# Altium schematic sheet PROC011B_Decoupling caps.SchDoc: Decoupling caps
size 431 x 279 mm; Date: Not shown in title block; ApprovedBy: Not shown in title block; CheckedBy: Not shown in title block; Author: Not shown in title block; CompanyName: Not shown in title block; Engineer: Not shown in title block; Organization: Not shown in title block; Address1: Not shown in title block; Address2: Not shown in title block; Address3: Not shown in title block; Address4: Not shown in title block; DocumentNumber: 1; Revision: Use project parameter SCH_Rev; SheetNumber: 3; SheetTotal: 17; PageSetup: Record=PageOptions¦CenterHorizontal=True¦CenterVertical=True¦PrintScale=1.00¦XCorrection=1.00¦YCorrection=1.00¦PrintKind=0¦BorderSize=5000000¦LeftOffset=0¦BottomOffset=0¦Orientation=2¦PaperLength=1000¦PaperWidth=1000¦Scale=100¦PaperSource=15¦PrintQuality=600¦MediaType=1¦DitherType=10¦PaperKind=Letter¦PrintScaleMode=1
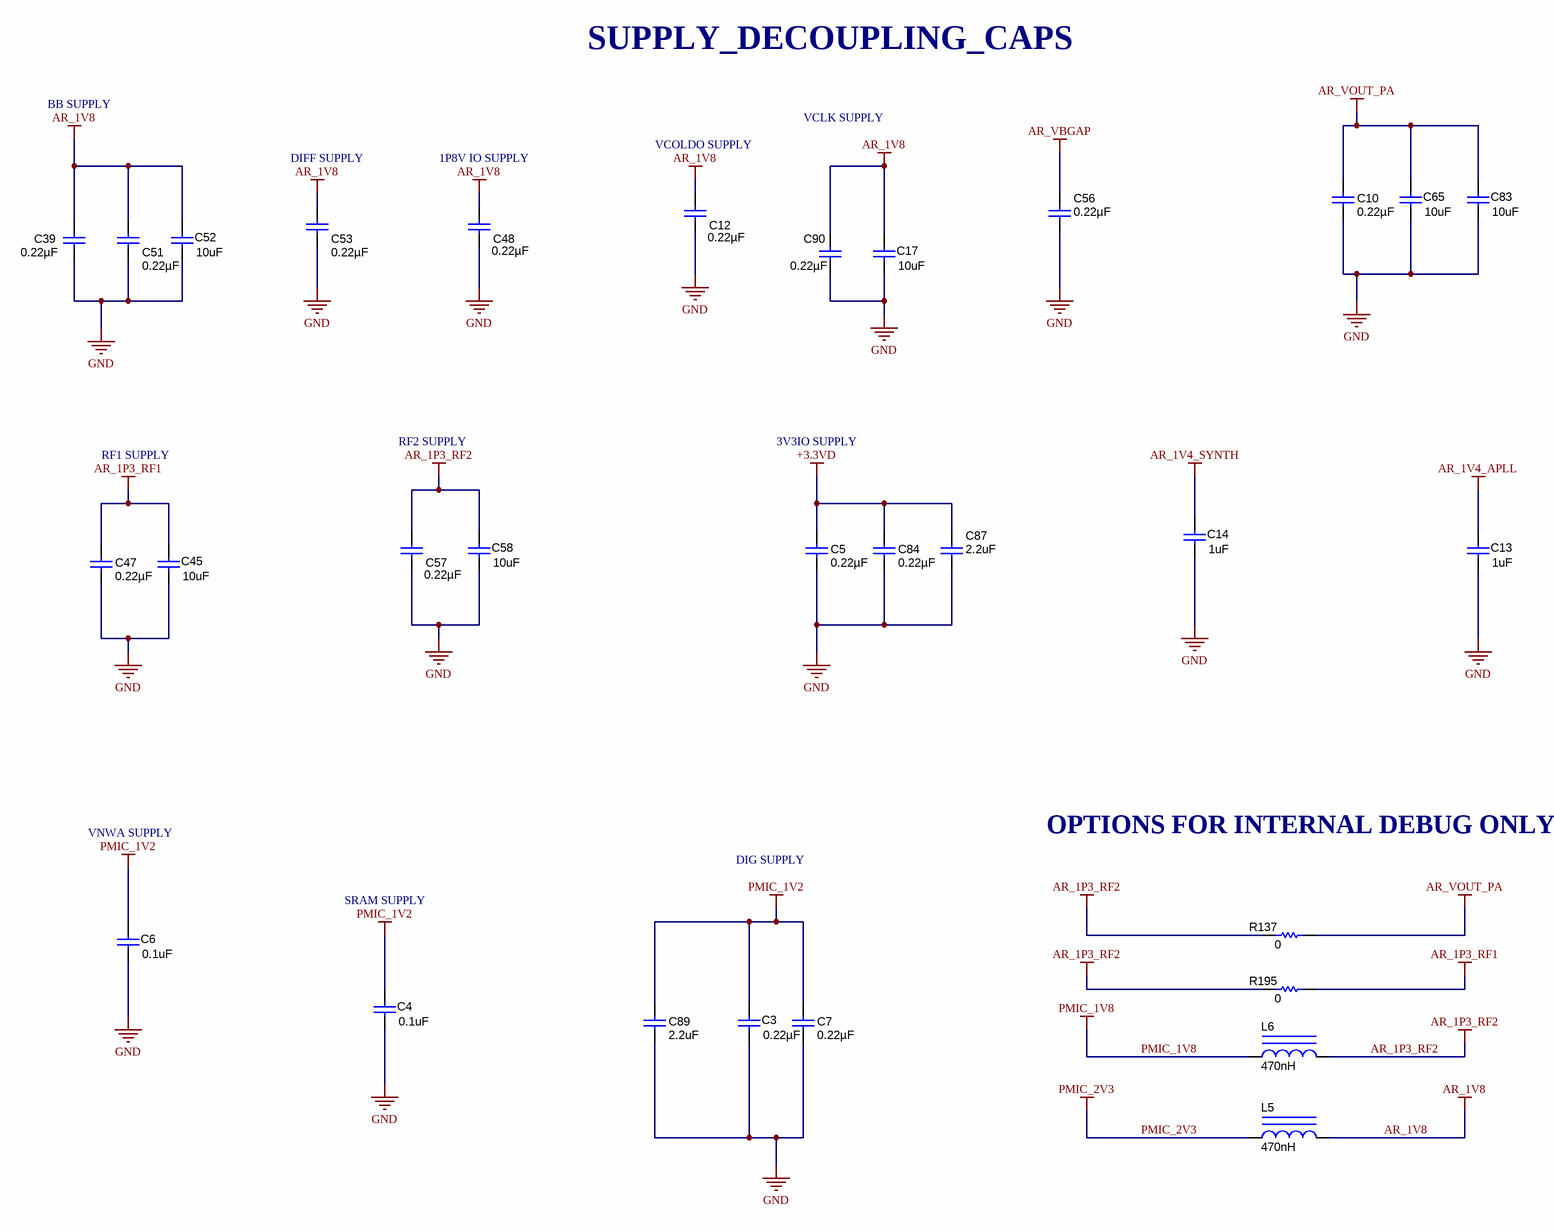
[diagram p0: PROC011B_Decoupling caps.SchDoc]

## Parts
C3  ValueDisplayed: 0.22µF  [0402L]  (hidden comment: GCM155R71C224KE02D)
C4  ValueDisplayed: 0.1uF  [0402L]  (hidden comment: GCM155R71C104KA55D)
C5  ValueDisplayed: 0.22µF  [0402L]  (hidden comment: GCM155R71C224KE02D)
C6  ValueDisplayed: 0.1uF  [0402L]  (hidden comment: GCM155R71C104KA55D)
C7  ValueDisplayed: 0.22µF  [0402L]  (hidden comment: GCM155R71C224KE02D)
C10  ValueDisplayed: 0.22µF  [0402L]  (hidden comment: GCM155R71C224KE02D)
C12  ValueDisplayed: 0.22µF  [0402L]  (hidden comment: GCM155R71C224KE02D)
C13  ValueDisplayed: 1uF  [0603]  (hidden comment: GCM188R71C105KA64D)
C14  ValueDisplayed: 1uF  [0603]  (hidden comment: GCM188R71C105KA64D)
C17  ValueDisplayed: 10uF  [0805_HV]  (hidden comment: GCM21BR71A106KE22L)
C39  ValueDisplayed: 0.22µF  [0402L]  (hidden comment: GCM155R71C224KE02D)
C45  ValueDisplayed: 10uF  [0805_HV]  (hidden comment: GCM21BR71A106KE22L)
C47  ValueDisplayed: 0.22µF  [0402L]  (hidden comment: GCM155R71C224KE02D)
C48  ValueDisplayed: 0.22µF  [0402L]  (hidden comment: GCM155R71C224KE02D)
C51  ValueDisplayed: 0.22µF  [0402L]  (hidden comment: GCM155R71C224KE02D)
C52  ValueDisplayed: 10uF  [0805_HV]  (hidden comment: GCM21BR71A106KE22L)
C53  ValueDisplayed: 0.22µF  [0402L]  (hidden comment: GCM155R71C224KE02D)
C56  ValueDisplayed: 0.22µF  [0402L]  (hidden comment: GCM155R71C224KE02D)
C57  ValueDisplayed: 0.22µF  [0402L]  (hidden comment: GCM155R71C224KE02D)
C58  ValueDisplayed: 10uF  [0805_HV]  (hidden comment: GCM21BR71A106KE22L)
C65  ValueDisplayed: 10uF  [0805_HV]  (hidden comment: GCM21BR71A106KE22L)
C83  ValueDisplayed: 10uF  [0805_HV]  (hidden comment: GCM21BR71A106KE22L)
C84  ValueDisplayed: 0.22µF  [0402L]  (hidden comment: GCM155R71C224KE02D)
C87  ValueDisplayed: 2.2uF  [0603]  (hidden comment: GCM188R70J225KE22D)
C89  ValueDisplayed: 2.2uF  [0603]  (hidden comment: GCM188R70J225KE22D)
C90  ValueDisplayed: 0.22µF  [0402L]  (hidden comment: GCM155R71C224KE02D)
L5  ValueDisplayed: 470nH  [DFE252012P]  (hidden comment: DFE252012P-R47M=P2)
L6  ValueDisplayed: 470nH  [DFE252012P]  (hidden comment: DFE252012P-R47M=P2)
R137  ValueDisplayed: 0  [0603]  (hidden comment: MCT06030Z0000ZP500)
R195  ValueDisplayed: 0  [0603]  (hidden comment: MCT06030Z0000ZP500)

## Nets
+3.3VD: C5.2 C84.2 C87.2
AR_1P3_RF1: C45.2 C47.2 R195.2
AR_1P3_RF2: C57.2 C58.2 L6.2 R137.1 R195.1
AR_1V4_APLL: C13.2
AR_1V4_SYNTH: C14.2
AR_1V8: C12.2 C17.2 C39.2 C48.2 C51.2 C52.2 C53.2 C90.2 L5.2
AR_VBGAP: C56.2
AR_VOUT_PA: C10.2 C65.2 C83.2 R137.2
GND: C3.1 C4.1 C5.1 C6.1 C7.1 C10.1 C12.1 C13.1 C14.1 C17.1 C39.1 C45.1 C47.1 C48.1 C51.1 C52.1 C53.1 C56.1 C57.1 C58.1 C65.1 C83.1 C84.1 C87.1 C89.1 C90.1
PMIC_1V2: C3.2 C4.2 C6.2 C7.2 C89.2
PMIC_1V8: L6.1
PMIC_2V3: L5.1

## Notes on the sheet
- SUPPLY_DECOUPLING_CAPS
- BB SUPPLY
- DIFF SUPPLY
- 1P8V IO SUPPLY
- VCOLDO SUPPLY
- VCLK SUPPLY
- RF1 SUPPLY
- RF2 SUPPLY
- 3V3IO SUPPLY
- VNWA SUPPLY
- OPTIONS FOR INTERNAL DEBUG ONLY
- SRAM SUPPLY
- DIG SUPPLY

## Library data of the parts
C3 C5 C7 C10 C12 C39 C47 C48 C51 C53 C56 C57 C84 C90 = CMP-0078265-1: CAP, CERM, 0.22 µF, 16 V,+/- 10%, X7R, AEC-Q200 Grade 1, 0402; Manufacturer: MuRata; TaMin_C: -55°C; Polarized: N; SizeAreaWB_mm2: 3; U/M: EA; Value: 0.22uF; TaMax_C: 125°C; SizeZ_mm: 0.6; SizeX_mm: 1; SizeY_mm: 0.5; Cap_Case: 0402; Value2: 16V; CompType: Capacitor; AEC Qualified: Y; Cap_F: 220nF; AEC Category: Q200
C4 C6 = CMP-0006351-2: CAP, CERM, 0.1 uF, 16 V, +/- 10%, X7R, 0402; Manufacturer: MuRata; TaMin_C: -55°C; Polarized: N; SizeAreaWB_mm2: 3; Value1: Unknown; U/M: EA; Value: 0.1uF; TaMax_C: 125°C; SizeZ_mm: 0.6; SizeX_mm: 1; SizeY_mm: 0.5; Cap_Case: 0402; Value2: 16V; Cap_F: 100nF; AEC Category: Q200
C13 C14 = CMP-0007136-5: CAP, CERM, 1 uF, 16 V, +/- 10%, X7R, AEC-Q200 Grade 1, 0603; Manufacturer: MuRata; TaMin_C: -55°C; Polarized: N; SizeAreaWB_mm2: 4.68; Value1: Unknown; U/M: EA; Value: 1uF; TaMax_C: 125°C; SizeZ_mm: 1; SizeX_mm: 1.6; SizeY_mm: 0.8; Value2: 16V; SizeArea_mm2: 1.28; AEC Qualified: Y; Cap_F: 1µF; AEC Category: Q200
C17 C45 C52 C58 C65 = CMP-0008017-2: CAP, CERM, 10 uF, 10 V, +/- 10%, X7R, 0805; Manufacturer: MuRata; TaMin_C: -55°C; Polarized: N; SizeAreaWB_mm2: 6.75; Value1: Unknown; U/M: EA; Value: 10uF; TaMax_C: 125°C; SizeZ_mm: 1.45; SizeX_mm: 2; SizeY_mm: 1.25; Cap_Case: 0805; Value2: 10V; SizeArea_mm2: 2.5; CompType: Capacitor; Cap_F: 10µF; AEC Category: Q200
C83 = CMP-0008017-2: CAP, CERM, 10 uF, 10 V, +/- 10%, X7R, 0805; Manufacturer: MuRata; TaMin_C: -55°C; Polarized: N; SizeAreaWB_mm2: 6.75; Value1: Unknown; U/M: EA; Value: 10uF; TaMax_C: 125°C; SizeZ_mm: 1.45; SizeX_mm: 2; SizeY_mm: 1.25; Cap_Case: 0805; Value2: 10V; SizeArea_mm2: 2.5; CompType: Capacitor; Cap_F: 10µF; AEC Category: Q200; INSTYALATION: DNP
C87 C89 = CMP-0007134-5: CAP, CERM, 2.2 uF, 6.3 V, +/- 10%, X7R, AEC-Q200 Grade 1, 0603; Manufacturer: MuRata; TaMin_C: -55°C; Polarized: N; SizeAreaWB_mm2: 4.68; Value1: Unknown; U/M: EA; Value: 2.2uF; TaMax_C: 125°C; SizeZ_mm: 1; SizeX_mm: 1.6; SizeY_mm: 0.8; Value2: 6.3V; SizeArea_mm2: 1.28; AEC Qualified: Y; Cap_F: 2.2µF; AEC Category: Q200
L5 L6 = CMP-0058946-1: Inductor, Shielded, 470 nH, 4.7 A, 0.021 ohm, SMD; Manufacturer: MuRata Toko; Isat: 6.4A @ 30% inductance drop; Irms: 4.7A @ 40C rise; SizeAreaWB_mm2: 10.5; DCR_ohm: 0.021; Value: 470nH; Imax_A: 4.7A; SizeZ_mm: 1.2; SizeX_mm: 2.5; SizeY_mm: 2; SizeArea_mm2: 5; AEC Category: Q200; INSTALATION: DNP
R137 R195 = CMP-0025884-3: RES, 0, 5%, 0.125 W, 0603; Manufacturer: Vishay/Beyschlag; Power_W: 125mW; TempCo: ppm/C; Value_Code: 0000; U/M: EA; Value: 0; EIA_Code: E24; SizeX_mm: 1.6; SizeY_mm: 0.8; SizeZ_mm: 1; Value2: 0.125W; SizeArea_mm2: 1.28; CompType: Resistor; AEC Qualified: N; AEC Category: Q200; INSTALATION: DNP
